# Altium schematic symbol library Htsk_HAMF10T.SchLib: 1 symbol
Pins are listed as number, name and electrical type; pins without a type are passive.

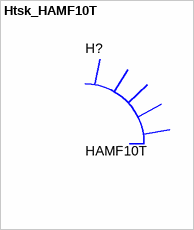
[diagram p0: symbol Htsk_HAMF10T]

## Htsk_HAMF10T
designator H?, comment HAMF10T
HEATSINK PFE1000F; Manufacturer: TDK-Lambda Americas Inc
footprint HSINK_518-95AB
footprint Htsk_HAMF10T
